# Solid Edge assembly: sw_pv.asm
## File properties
Author: Sham
Template: Sync Iso Assembly.asm
Last saved by: Sham
Revision: 3
Application: Solid Edge
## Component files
base.par
Screw.par
moveable jaw.par
handle.par
handle screw.par
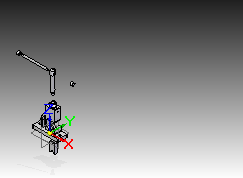
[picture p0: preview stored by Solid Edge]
